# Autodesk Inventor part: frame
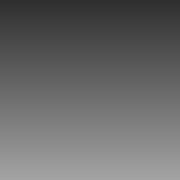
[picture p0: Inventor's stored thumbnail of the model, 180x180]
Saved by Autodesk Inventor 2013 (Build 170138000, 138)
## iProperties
Created: 2009-11
Part Number: frame
Document SubType Name: Modeling
Designer: pokornp
Density: 1 g/cm^3
Material: Generic
Author: pokornp
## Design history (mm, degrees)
sketch "Sketch1"
  geometry: L1 (300, 0)-(300, -1960); L2 (1200, 0)-(1200, -1960); L3 (300, -980)-(1200, -980); 1 further point
  constraints: 6 end point, 2 horizontal alignment, 2 midpoint
  dimensions: "w" = 1960 distance of L2.start L2.end; "d5" = 900 distance between parallel lines of L1 L2; "d7" = 980 distance from line of L2.end L3 (= 0.5 x w)
sketch "3D Sketch1"
